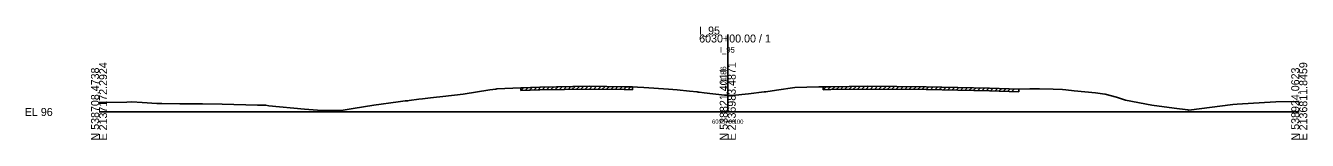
# Model space of a CAD drawing. Extents: x -12534 to 3403, y -1332 to 21983.
# Drawn here: x 974.3 to 1422.8, y 16490.3 to 16530.1 of the extents above; entities that cross this region are included whole.
import ezdxf

# ---------------------------------------------------------------- set-up
doc = ezdxf.new("R2010")
doc.units = 0
for name, color, linetype in [('RD_GPK_XS_Cell', 7, 'Continuous'), ('RD_XS_ExGround', 7, 'Continuous'), ('RD_XS_ExPaveRet', 7, 'Continuous'), ('RD_XS_TX_Baseline', 7, 'Continuous'), ('RD_XS_TX_Elev_EX', 7, 'Continuous'), ('RD_XS_TX_Station', 7, 'Continuous')]:
    doc.layers.add(name, color=color, linetype=linetype)

msp = doc.modelspace()

# ---------------------------------------------------------------- linework, layer by layer
at = {"layer": 'RD_GPK_XS_Cell'}
for p, q in [((1220, 16500), (1220, 16527.21)), ((1000, 16500), (1220, 16500)), ((1220, 16500), (1420, 16500))]:
    msp.add_line(p, q, dxfattribs=at)
at = {"layer": 'RD_XS_ExGround'}
msp.add_lwpolyline([(1000, 16503.28), (1001.14, 16503.31), (1009.72, 16503.5), (1011.5, 16503.55), (1015.13, 16503.35), (1020.27, 16502.95), (1021.97, 16502.95), (1028.3, 16502.9), (1032.72, 16502.84), (1036.25, 16502.84), (1043.12, 16502.78), (1055.45, 16502.41), (1057.41, 16502.42), (1058.42, 16502.35), (1059.45, 16502.2), (1071.85, 16501.01), (1077.93, 16500.51), (1082.28, 16500.52), (1085.41, 16500.62), (1088.9, 16501.19), (1096.12, 16502.36), (1104.72, 16503.58), (1107.14, 16503.88), (1107.94, 16503.86), (1108.49, 16503.98), (1111.85, 16504.46), (1113.17, 16504.6), (1116.02, 16504.98), (1117.05, 16505.1), (1120.32, 16505.45), (1127.47, 16506.27), (1136.77, 16507.74), (1138.86, 16508.03), (1139.23, 16508.1), (1147.61, 16508.53), (1154.19, 16508.77), (1171.57, 16509.06), (1183.79, 16508.88), (1186.68, 16508.81), (1188.4, 16508.66), (1190.61, 16508.63), (1199.25, 16507.99), (1202.31, 16507.77), (1206.65, 16507.31), (1209.34, 16507.03), (1209.65, 16506.99), (1210.06, 16506.92), (1211.79, 16506.69), (1218.84, 16505.93), (1220, 16505.86), (1221.45, 16505.77), (1222.75, 16505.86), (1226.12, 16506.25), (1227.32, 16506.38), (1232.7, 16507.06), (1233.28, 16507.12), (1237.12, 16507.71), (1243.46, 16508.63), (1251.83, 16508.82), (1252.96, 16508.83), (1253.42, 16508.82), (1256.06, 16508.84), (1268.97, 16509.07), (1289.46, 16508.84), (1311.65, 16508.39), (1321.88, 16508.06), (1325.74, 16508.1), (1327.87, 16508.14), (1329.15, 16508.11), (1333.88, 16508), (1337.12, 16507.84), (1338.36, 16507.79), (1341.29, 16507.46), (1348.66, 16506.73), (1351.11, 16506.38), (1352.11, 16506.22), (1356.09, 16505.15), (1359.18, 16504.16), (1368.4, 16502.45), (1376.28, 16501.37), (1381, 16500.74), (1381.41, 16500.68), (1396.76, 16502.6), (1398.26, 16502.71), (1407.85, 16503.36), (1411.84, 16503.56), (1418.9, 16503.74), (1420, 16503.74)], dxfattribs=at)
at = {"layer": 'RD_XS_ExPaveRet'}
for p, q in [((1147.61, 16507.53), (1148.65, 16508.57)), ((1147.61, 16507.53), (1147.61, 16508.53)), ((1147.61, 16507.53), (1154.19, 16507.77)), ((1149.11, 16507.58), (1150.15, 16508.62)), ((1150.61, 16507.64), (1151.65, 16508.68)), ((1152.11, 16507.69), (1153.15, 16508.73)), ((1153.61, 16507.75), (1154.64, 16508.78)), ((1154.19, 16507.77), (1171.57, 16508.06)), ((1155.11, 16507.79), (1156.13, 16508.8)), ((1156.61, 16507.81), (1157.63, 16508.83)), ((1158.11, 16507.84), (1159.13, 16508.85)), ((1159.61, 16507.86), (1160.63, 16508.88)), ((1161.11, 16507.88), (1162.13, 16508.9)), ((1162.61, 16507.91), (1163.63, 16508.93)), ((1164.11, 16507.93), (1165.13, 16508.95)), ((1165.61, 16507.96), (1166.63, 16508.98)), ((1167.11, 16507.98), (1168.13, 16509)), ((1168.61, 16508.01), (1169.63, 16509.03)), ((1170.11, 16508.03), (1171.13, 16509.05)), ((1171.57, 16508.06), (1183.79, 16507.88)), ((1171.61, 16508.06), (1172.6, 16509.04)), ((1173.11, 16508.04), (1174.1, 16509.02)), ((1174.61, 16508.01), (1175.6, 16509)), ((1176.11, 16507.99), (1177.1, 16508.98)), ((1177.61, 16507.97), (1178.6, 16508.96)), ((1179.11, 16507.95), (1180.1, 16508.93)), ((1180.61, 16507.93), (1181.6, 16508.91)), ((1182.11, 16507.9), (1183.1, 16508.89)), ((1183.61, 16507.88), (1184.59, 16508.86)), ((1183.79, 16507.88), (1186.68, 16507.81)), ((1185.11, 16507.85), (1186.09, 16508.83)), ((1186.68, 16508.81), (1186.68, 16507.81)), ((1253.42, 16507.82), (1254.42, 16508.83)), ((1253.42, 16507.82), (1253.42, 16508.82)), ((1253.42, 16507.82), (1256.06, 16507.84)), ((1254.92, 16507.83), (1255.92, 16508.84)), ((1256.06, 16507.84), (1268.97, 16508.07)), ((1256.42, 16507.84), (1257.44, 16508.86)), ((1257.92, 16507.87), (1258.94, 16508.89)), ((1259.42, 16507.9), (1260.44, 16508.92)), ((1260.92, 16507.93), (1261.94, 16508.94)), ((1262.42, 16507.95), (1263.44, 16508.97)), ((1263.92, 16507.98), (1264.94, 16509)), ((1265.42, 16508.01), (1266.44, 16509.03)), ((1266.92, 16508.03), (1267.94, 16509.05)), ((1268.42, 16508.06), (1269.42, 16509.07)), ((1268.97, 16508.07), (1289.46, 16507.84)), ((1269.92, 16508.06), (1270.91, 16509.05)), ((1271.42, 16508.04), (1272.41, 16509.03)), ((1272.92, 16508.03), (1273.91, 16509.02)), ((1274.42, 16508.01), (1275.41, 16509)), ((1275.92, 16507.99), (1276.91, 16508.98)), ((1277.42, 16507.98), (1278.41, 16508.97)), ((1278.92, 16507.96), (1279.91, 16508.95)), ((1280.42, 16507.94), (1281.41, 16508.93)), ((1281.92, 16507.93), (1282.91, 16508.91)), ((1283.42, 16507.91), (1284.41, 16508.9)), ((1284.92, 16507.89), (1285.91, 16508.88)), ((1286.42, 16507.87), (1287.41, 16508.86)), ((1287.92, 16507.86), (1288.91, 16508.85)), ((1289.42, 16507.84), (1290.4, 16508.82)), ((1289.46, 16507.84), (1311.65, 16507.39)), ((1290.92, 16507.81), (1291.9, 16508.79)), ((1292.42, 16507.78), (1293.4, 16508.76)), ((1293.92, 16507.75), (1294.9, 16508.73)), ((1295.42, 16507.72), (1296.4, 16508.7)), ((1296.92, 16507.69), (1297.9, 16508.67)), ((1298.42, 16507.66), (1299.4, 16508.64)), ((1299.92, 16507.63), (1300.9, 16508.61)), ((1301.42, 16507.6), (1302.4, 16508.58)), ((1302.92, 16507.57), (1303.9, 16508.55)), ((1304.42, 16507.54), (1305.4, 16508.52)), ((1305.92, 16507.51), (1306.9, 16508.49)), ((1307.42, 16507.47), (1308.4, 16508.45)), ((1308.92, 16507.44), (1309.9, 16508.42)), ((1310.42, 16507.41), (1311.4, 16508.39)), ((1311.65, 16507.39), (1321.88, 16507.06)), ((1311.92, 16507.38), (1312.89, 16508.35)), ((1313.42, 16507.33), (1314.39, 16508.3)), ((1314.92, 16507.28), (1315.89, 16508.25)), ((1316.42, 16507.24), (1317.39, 16508.2)), ((1317.92, 16507.19), (1318.89, 16508.16)), ((1319.42, 16507.14), (1320.39, 16508.11)), ((1321.88, 16508.06), (1321.88, 16507.06))]:
    msp.add_line(p, q, dxfattribs=at)

# ---------------------------------------------------------------- texts
at = {"layer": 'RD_GPK_XS_Cell'}
for s, p in [('I_95', (1210, 16527.21)), ('6030+00.00 / 1', (1210, 16524.41)), ('EL 96', (974, 16498.6))]:
    msp.add_text(s, height=2.8, dxfattribs=at).set_placement(p)
for s, p in [('N 538708.4738', (1000, 16490)), ('E 2137172.2924', (1002.8, 16490)), ('N 538821.4011', (1220, 16490)), ('E 2136983.4871', (1222.8, 16490)), ('N 538924.0623', (1420, 16490)), ('E 2136811.8459', (1422.8, 16490))]:
    msp.add_text(s, height=2.8, rotation=90, dxfattribs=at).set_placement(p)
at = {"layer": 'RD_XS_TX_Baseline'}
msp.add_text('I_95', height=2, dxfattribs=at).set_placement((1217.28, 16520.86))
at = {"layer": 'RD_XS_TX_Elev_EX'}
msp.add_text('101.86', height=2, rotation=90, dxfattribs=at).set_placement((1219.5, 16507.86))
at = {"layer": 'RD_XS_TX_Station'}
msp.add_text('6030+00.00', height=1.5, dxfattribs=at).set_placement((1214.5, 16495.86))

doc.saveas('drawing.dxf')
